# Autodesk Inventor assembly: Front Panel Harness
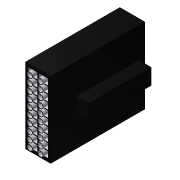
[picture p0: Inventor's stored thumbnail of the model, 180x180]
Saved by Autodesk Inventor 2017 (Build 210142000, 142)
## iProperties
Created: 2007-02
Part Number: Front Panel Harness
Document SubType Name: Assembly
Designer: DanielSeverino
Author: DanielSeverino
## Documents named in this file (2)
- C:\Users\DanielSeverino\Desktop\01\Front Panel Harness.iam
- C:\Users\DanielSeverino\Desktop\01\Front Panel Connector.ipt
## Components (1 placed, 1 different names)
1. Front Panel Connector:1
